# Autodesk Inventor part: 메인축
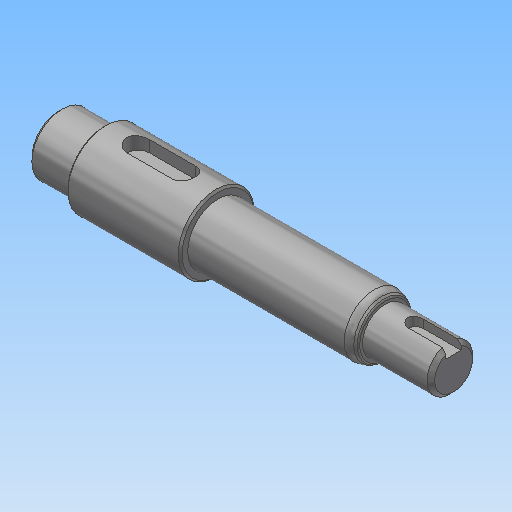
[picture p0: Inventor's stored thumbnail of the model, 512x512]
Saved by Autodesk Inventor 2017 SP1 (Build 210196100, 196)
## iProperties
Created: 2019-03
Part Number: 메인축
Material: 강철, 연강
Document SubType Name: Modeling
Designer: mduedu
Density: 1 g/cm^3
Appearance: 강철
Author: mduedu
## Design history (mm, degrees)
sketch "스케치1"
  geometry: L1 (0, 0)-(12, 0); L2 (12, 0)-(12, 8); L3 (12, 8)-(0, 8); L4 (0, 8)-(0, 0); L5 (12, 0)-(42, 0); L6 (42, 0)-(42, 10); L7 (42, 10)-(12, 10); L8 (12, 10)-(12, 0); L9 (42, 0)-(86, 0); L10 (86, 0)-(86, 8); L11 (86, 8)-(42, 8); L12 (42, 8)-(42, 0); L13 (86, 0)-(104, 0); L14 (104, 0)-(104, 6); L15 (104, 6)-(86, 6); L16 (86, 6)-(86, 0)
  constraints: 32 end point, 8 parallel, 4 horizontal, 4 perpendicular
  dimensions: "d0" = 16 diameter of L3 L1; "d2" = 20 diameter of L7 L5; "d3" = 16 diameter of L11 L9; "d4" = 12 diameter of L15 L13; "d5" = 12 distance of L2.end L3.end; "d6" = 30 distance of L6.end L7.end; "d7" = 86 distance between parallel lines of L10 L4; "d8" = 104 distance between parallel lines of L14 L4
revolve "회전1" sketch "스케치1" stored, may be unused: angle "d9" = 90 deg
node "작업 평면1"
sketch "스케치2" dims "d10" = 18
  geometry: L1 (6, -3)-(-6, -3); L2 (-6, -3)-(-6, 3); L3 (-6, 3)-(6, 3); L4 (6, 3)-(6, -3); L5 (15, 10)-(15, -10) reference; 3 further points
  constraints: 8 end point, 2 midpoint, 2 parallel, 2 vertical alignment, 1 horizontal, 1 horizontal alignment, 1 perpendicular, 4 other
  dimensions: "d12" = 6 distance between parallel lines of L3 L1; "d13" = 6 dimension on L5
extrude "돌출1" cut sketch "스케치2" distance "d14" = 3.5; taper "d15" = 0 deg
node "작업 평면2"
sketch "스케치3"
  geometry: L1 (-9, 6)-(-9, -6) reference; L2 (1, -2)-(-9, -2); L3 (1, 2)-(-9, 2); A1 r 2 centre (1, 0) between (1, -2) and (1, 2); 2 further points
  constraints: 4 end point, 2 point on circle, 2 point on line, 2 tangent, 1 centre point, 1 horizontal alignment, 1 midpoint, 1 parallel, 1 perpendicular
  dimensions: "d16" = 12 dimension on A1 L1; "d17" = 4 distance between parallel lines of L3 L2
extrude "돌출2" cut sketch "스케치3" distance "d18" = 2.5; taper "d19" = 0 deg
chamfer "모따기1" distance "d20" = 1; stored, may be unused: second distance "d21" = 2, angle "d22" = 45 deg
chamfer "모따기2" distance "d23" = 0.5; stored, may be unused: second distance "d24" = 2, angle "d25" = 45 deg
chamfer "모따기3" distance "d26" = 1.73; stored, may be unused: second distance "d27" = 2, angle "d28" = 30 deg
fillet "모깎기2" dims "d31" = 0.5, "d32" = 4
node "솔리드1"
